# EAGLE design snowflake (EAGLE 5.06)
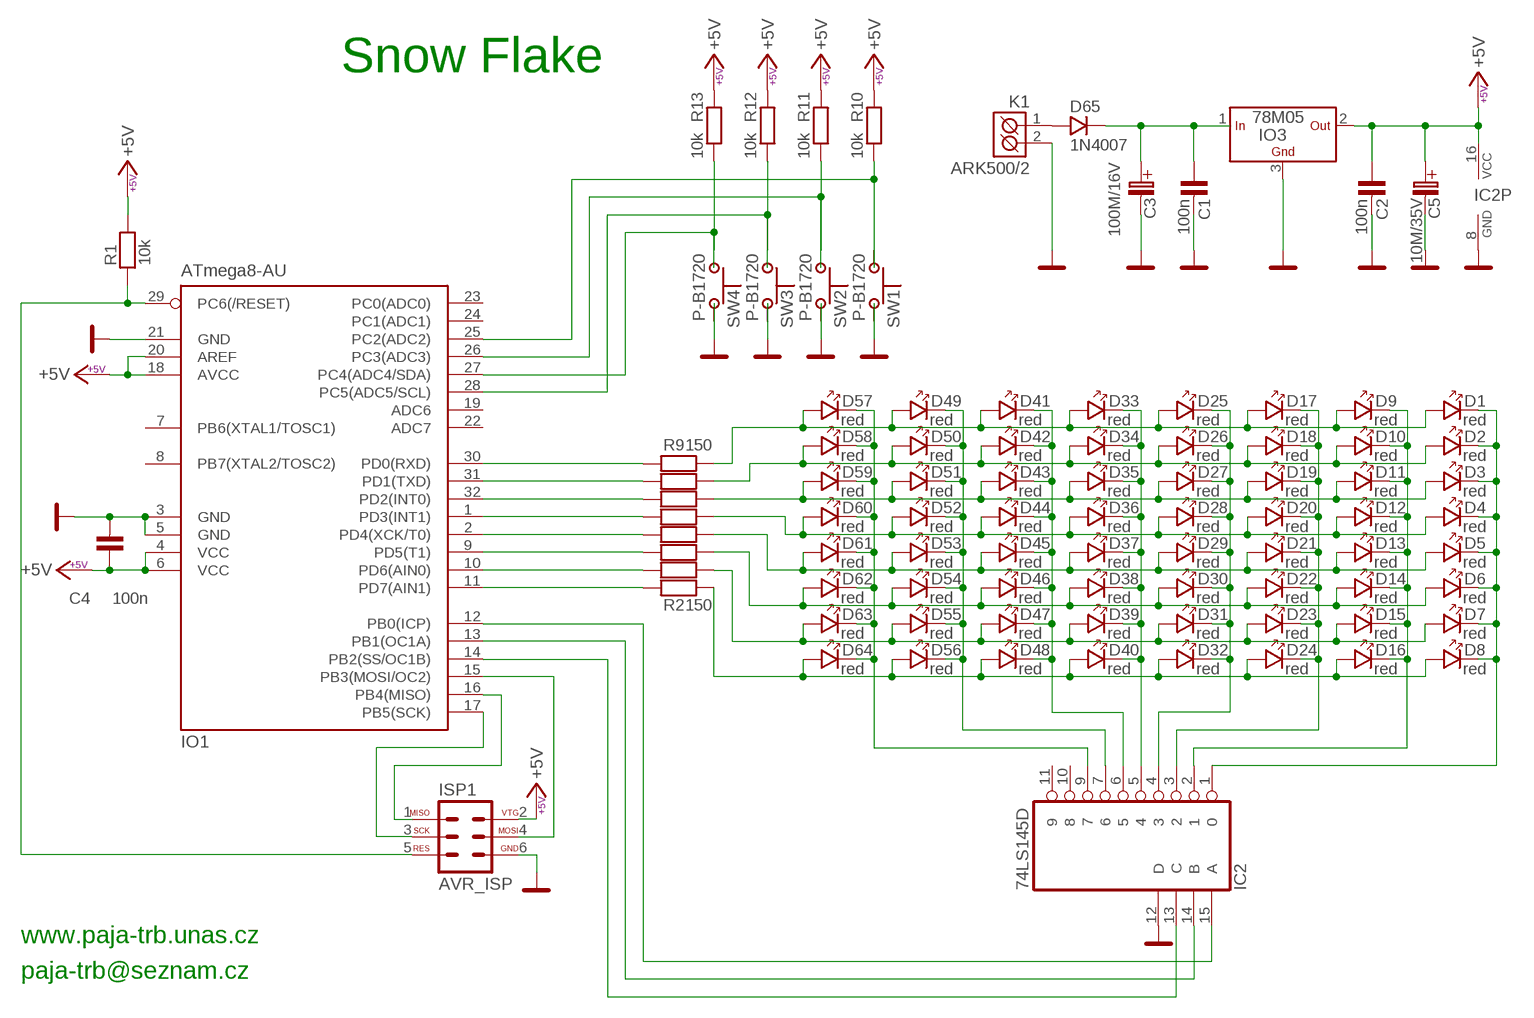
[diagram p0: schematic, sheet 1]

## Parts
C1  100n  C-KERAMIK_SMD_1206  [1206]
C2  100n  C-KERAMIK_SMD_1206  [1206]
C3  100M/16V  100M/16V_SMD  [C_EL-SMD_D]
C4  100n  C-KERAMIK_SMD_1206  [1206]
C5  10M/35V  10M/35V_SMD  [C_EL-SMD_C]
D1  red  LED_5  [LED_5]
D2  red  LED_5  [LED_5]
D3  red  LED_5  [LED_5]
D4  red  LED_5  [LED_5]
D5  red  LED_5  [LED_5]
D6  red  LED_5  [LED_5]
D7  red  LED_5  [LED_5]
D8  red  LED_5  [LED_5]
D9  red  LED_5  [LED_5]
D10  red  LED_5  [LED_5]
D11  red  LED_5  [LED_5]
D12  red  LED_5  [LED_5]
D13  red  LED_5  [LED_5]
D14  red  LED_5  [LED_5]
D15  red  LED_5  [LED_5]
D16  red  LED_5  [LED_5]
D17  red  LED_5  [LED_5]
D18  red  LED_5  [LED_5]
D19  red  LED_5  [LED_5]
D20  red  LED_5  [LED_5]
D21  red  LED_5  [LED_5]
D22  red  LED_5  [LED_5]
D23  red  LED_5  [LED_5]
D24  red  LED_5  [LED_5]
D25  red  LED_5  [LED_5]
D26  red  LED_5  [LED_5]
D27  red  LED_5  [LED_5]
D28  red  LED_5  [LED_5]
D29  red  LED_5  [LED_5]
D30  red  LED_5  [LED_5]
D31  red  LED_5  [LED_5]
D32  red  LED_5  [LED_5]
D33  red  LED_5  [LED_5]
D34  red  LED_5  [LED_5]
D35  red  LED_5  [LED_5]
D36  red  LED_5  [LED_5]
D37  red  LED_5  [LED_5]
D38  red  LED_5  [LED_5]
D39  red  LED_5  [LED_5]
D40  red  LED_5  [LED_5]
D41  red  LED_5  [LED_5]
D42  red  LED_5  [LED_5]
D43  red  LED_5  [LED_5]
D44  red  LED_5  [LED_5]
D45  red  LED_5  [LED_5]
D46  red  LED_5  [LED_5]
D47  red  LED_5  [LED_5]
D48  red  LED_5  [LED_5]
D49  red  LED_5  [LED_5]
D50  red  LED_5  [LED_5]
D51  red  LED_5  [LED_5]
D52  red  LED_5  [LED_5]
D53  red  LED_5  [LED_5]
D54  red  LED_5  [LED_5]
D55  red  LED_5  [LED_5]
D56  red  LED_5  [LED_5]
D57  red  LED_5  [LED_5]
D58  red  LED_5  [LED_5]
D59  red  LED_5  [LED_5]
D60  red  LED_5  [LED_5]
D61  red  LED_5  [LED_5]
D62  red  LED_5  [LED_5]
D63  red  LED_5  [LED_5]
D64  red  LED_5  [LED_5]
D65  1N4007  1N4007_SM-1  [SM-1]
IC2  74LS145D  74145D  [SO16]
IO1  ATmega8-AU  MEGA8-AI  [TQFP32-08]
IO3  78M05  78_SMD_SMD  [D2PAK]
ISP1  AVR_ISP  [MLW06G]
K1  ARK500/2  [ARK500/2]
R1  10k  R_SMD_1206  [1206]
R2  150  R_SMD_1206  [1206]
R3  150  R_SMD_1206  [1206]
R4  150  R_SMD_1206  [1206]
R5  150  R_SMD_1206  [1206]
R6  150  R_SMD_1206  [1206]
R7  150  R_SMD_1206  [1206]
R8  150  R_SMD_1206  [1206]
R9  150  R_SMD_1206  [1206]
R10  10k  R_SMD_1206  [1206]
R11  10k  R_SMD_1206  [1206]
R12  10k  R_SMD_1206  [1206]
R13  10k  R_SMD_1206  [1206]
SW1  P-B1720  [P-B1720]
SW2  P-B1720  [P-B1720]
SW3  P-B1720  [P-B1720]
SW4  P-B1720  [P-B1720]

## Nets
+: D65.A K1.1(K1)
+5V: C2.1 C4.1 C5.+(C_EL+) IC2.16(VCC) IO1.4(VCC) IO1.6(VCC) IO1.18(AVCC) IO1.20(AREF) IO3.2(OUT) ISP1.2 R1.2 R10.1 R11.1 R12.1 R13.1
GND: C1.2 C2.2 C3.-(C_EL-) C4.2 C5.-(C_EL-) IC2.8(GND) IC2.12(D) IO1.3(GND) IO1.5(GND) IO1.21(GND) IO3.3(GND) ISP1.6 K1.2(K2) SW1.2 SW1.4 SW2.2 SW2.4 SW3.2 SW3.4 SW4.2 SW4.4
N$1: IO1.29(PC6(/RESET)) ISP1.5 R1.1
N$2: D5.A D13.A D21.A D29.A D37.A D45.A D53.A D61.A R5.2
N$4: IO1.27(PC4(ADC4/SDA)) R13.2 SW4.1 SW4.3
N$5: IO1.11(PD7(AIN1)) R2.1
N$6: IO1.10(PD6(AIN0)) R3.1
N$7: IO1.9(PD5(T1)) R4.1
N$8: IO1.2(PD4(XCK/T0)) R5.1
N$9: IO1.1(PD3(INT1)) R6.1
N$10: IO1.32(PD2(INT0)) R7.1
N$11: IO1.31(PD1(TXD)) R8.1
N$12: IO1.30(PD0(RXD)) R9.1
N$13: D1.K D2.K D3.K D4.K D5.K D6.K D7.K D8.K IC2.1
N$14: D1.A D9.A D17.A D25.A D33.A D41.A D49.A D57.A R9.2
N$15: D9.K D10.K D11.K D12.K D13.K D14.K D15.K D16.K IC2.2
N$16: D2.A D10.A D18.A D26.A D34.A D42.A D50.A D58.A R8.2
N$17: D3.A D11.A D19.A D27.A D35.A D43.A D51.A D59.A R7.2
N$18: D4.A D12.A D20.A D28.A D36.A D44.A D52.A D60.A R6.2
N$19: D6.A D14.A D22.A D30.A D38.A D46.A D54.A D62.A R4.2
N$20: D7.A D15.A D23.A D31.A D39.A D47.A D55.A D63.A R3.2
N$21: D8.A D16.A D24.A D32.A D40.A D48.A D56.A D64.A R2.2
N$22: D17.K D18.K D19.K D20.K D21.K D22.K D23.K D24.K IC2.3
N$23: D25.K D26.K D27.K D28.K D29.K D30.K D31.K D32.K IC2.4
N$24: D33.K D34.K D35.K D36.K D37.K D38.K D39.K D40.K IC2.5
N$25: D41.K D42.K D43.K D44.K D45.K D46.K D47.K D48.K IC2.6
N$26: D49.K D50.K D51.K D52.K D53.K D54.K D55.K D56.K IC2.7
N$27: D57.K D58.K D59.K D60.K D61.K D62.K D63.K D64.K IC2.9
N$28: IO1.15(PB3(MOSI/OC2)) ISP1.4
N$29: IO1.16(PB4(MISO)) ISP1.1
N$30: IO1.17(PB5(SCK)) ISP1.3
N$31: IO1.28(PC5(ADC5/SCL)) R12.2 SW3.1 SW3.3
N$32: IO1.26(PC3(ADC3)) R11.2 SW2.1 SW2.3
N$33: IO1.25(PC2(ADC2)) R10.2 SW1.1 SW1.3
N$34: IC2.13(C) IO1.14(PB2(SS/OC1B))
N$35: IC2.14(B) IO1.13(PB1(OC1A))
N$36: IC2.15(A) IO1.12(PB0(ICP))
N$38: C1.1 C3.+(C_EL+) D65.K IO3.1(IN)
Unconnected: IC2.10 IC2.11 IO1.7(PB6(XTAL1/TOSC1)) IO1.8(PB7(XTAL2/TOSC2)) IO1.19(ADC6) IO1.22(ADC7) IO1.23(PC0(ADC0)) IO1.24(PC1(ADC1))

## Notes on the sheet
- Snow Flake
- www.paja-trb.unas.cz
- paja-trb@seznam.cz

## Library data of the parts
C1 C2 C4 = #PaJa_31:C-KERAMIK: Kondenzator - keramicky
C3 = #PaJa_C-el_2:100M/16V
C5 = #PaJa_C-el_2:10M/35V
D1-D64 = #PaJa_31:LED: LED - jednobarevna
D65 = #PaJa_31:1N4007: Usmernovaci dioda - 1A, 1000V
IC2 = 74xx-eu:74*145: BCD to decimal DECODER/DRIVER
IO1 = atmel:MEGA8: MICROCONTROLLER 8 Kbytes FLASH, 1 kbytes SRAM, 512 bytes EEPROM, USART, 6-channel 10 bit ADC, 2-channel 8 bit ADC Pin compatible with Atmega48, ATMega88, ATMega168 Source: avr.lbr
IO3 = #PaJa_31:78??: Stabilizátor - 1A a 1,5A ?? - napeti => 05, 06, 08, 09, 12, 15, 18, 20, 24 => 1,5A ?? - napeti => 10, 12, 15, 18 => 1A S ?? - napeti => 05, 09, 10, 12, 15, 18, 24 => 2A T ?? - napeti => 05 => 3A
ISP1 = #PaJa_31:AVR_ISP: AVR ISP konektor (dle standardu)
K1 = #PaJa_konektory:ARK500/2: Svorkovnice - roztec 5mm - dvojita
R1-R13 = #PaJa_31:R: Rezistor
SW1-SW4 = #PaJa_prepinace:P-B1720: &micro;-tlacitko

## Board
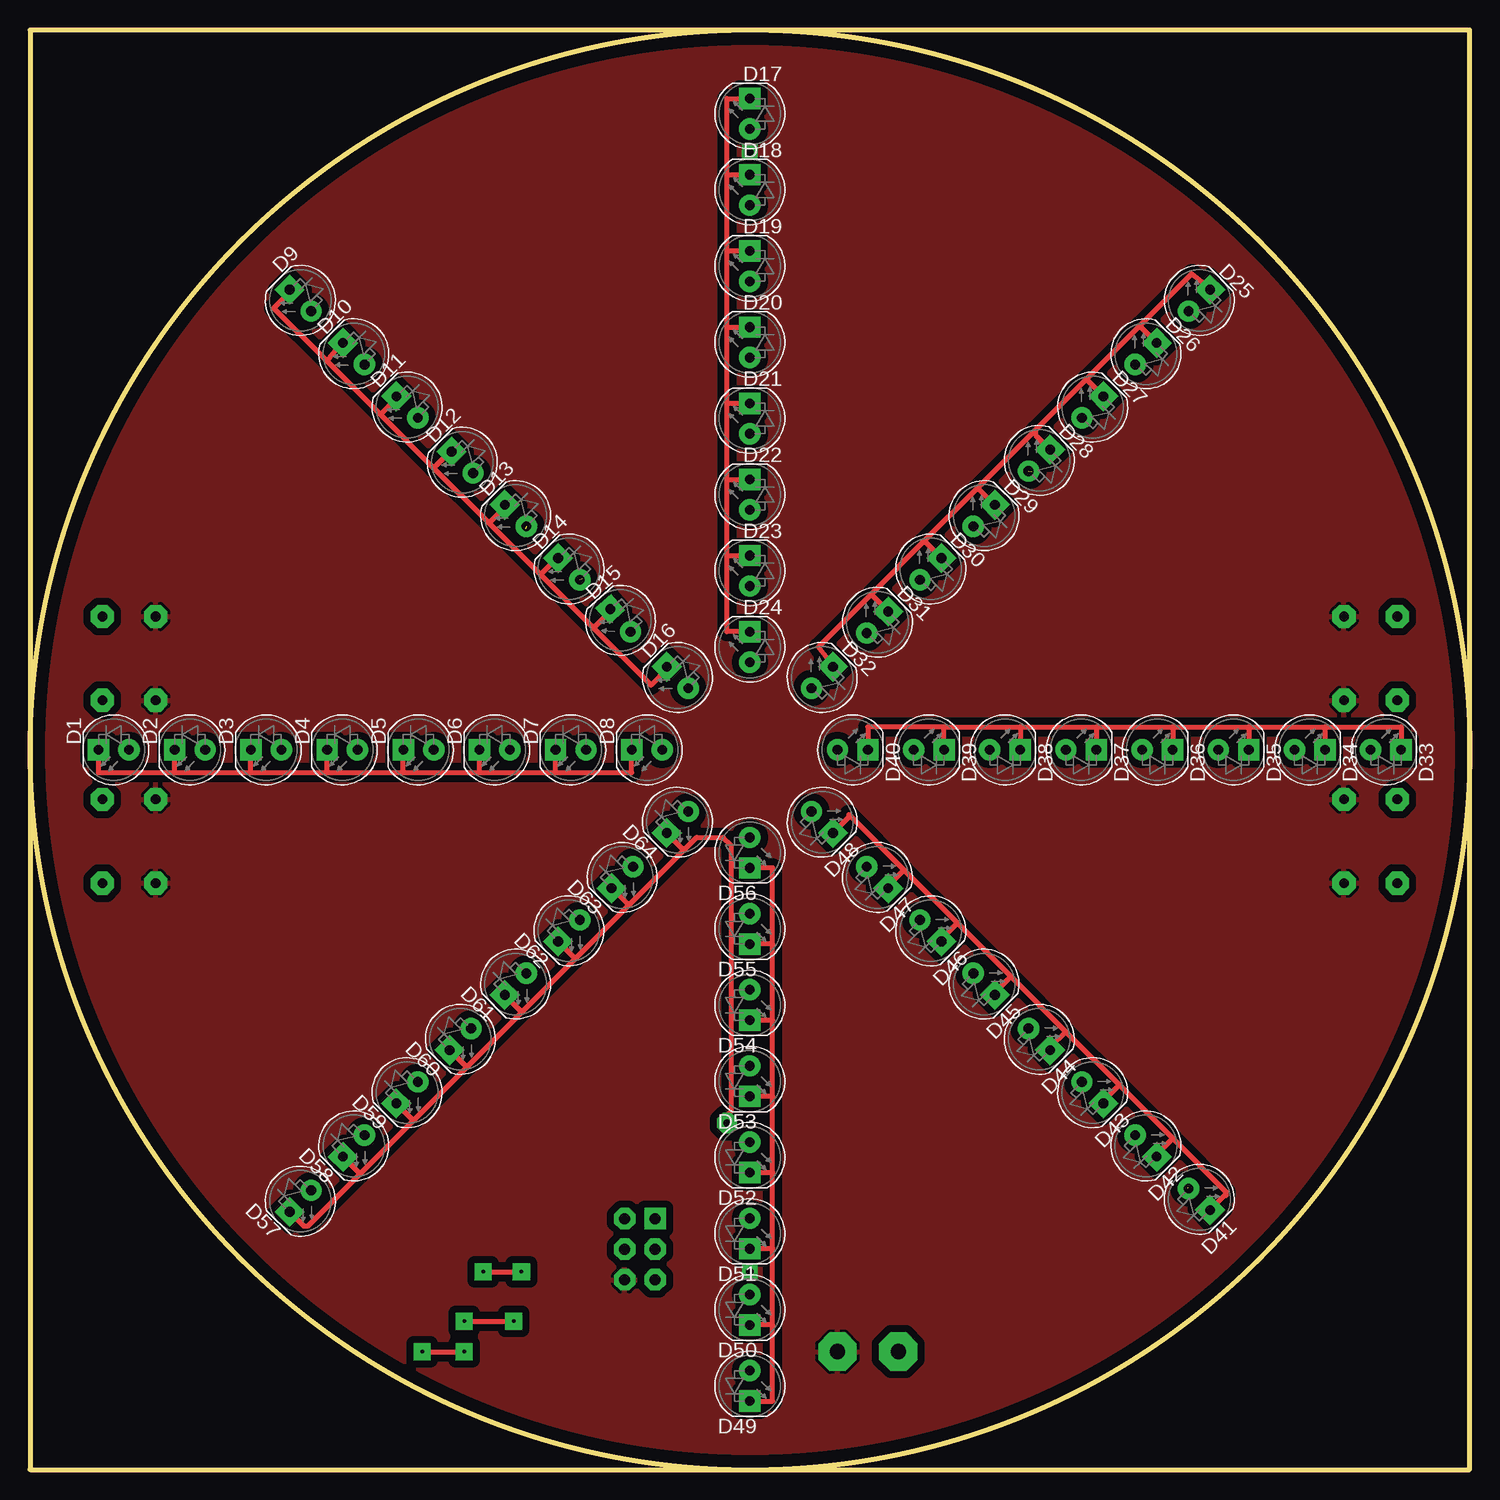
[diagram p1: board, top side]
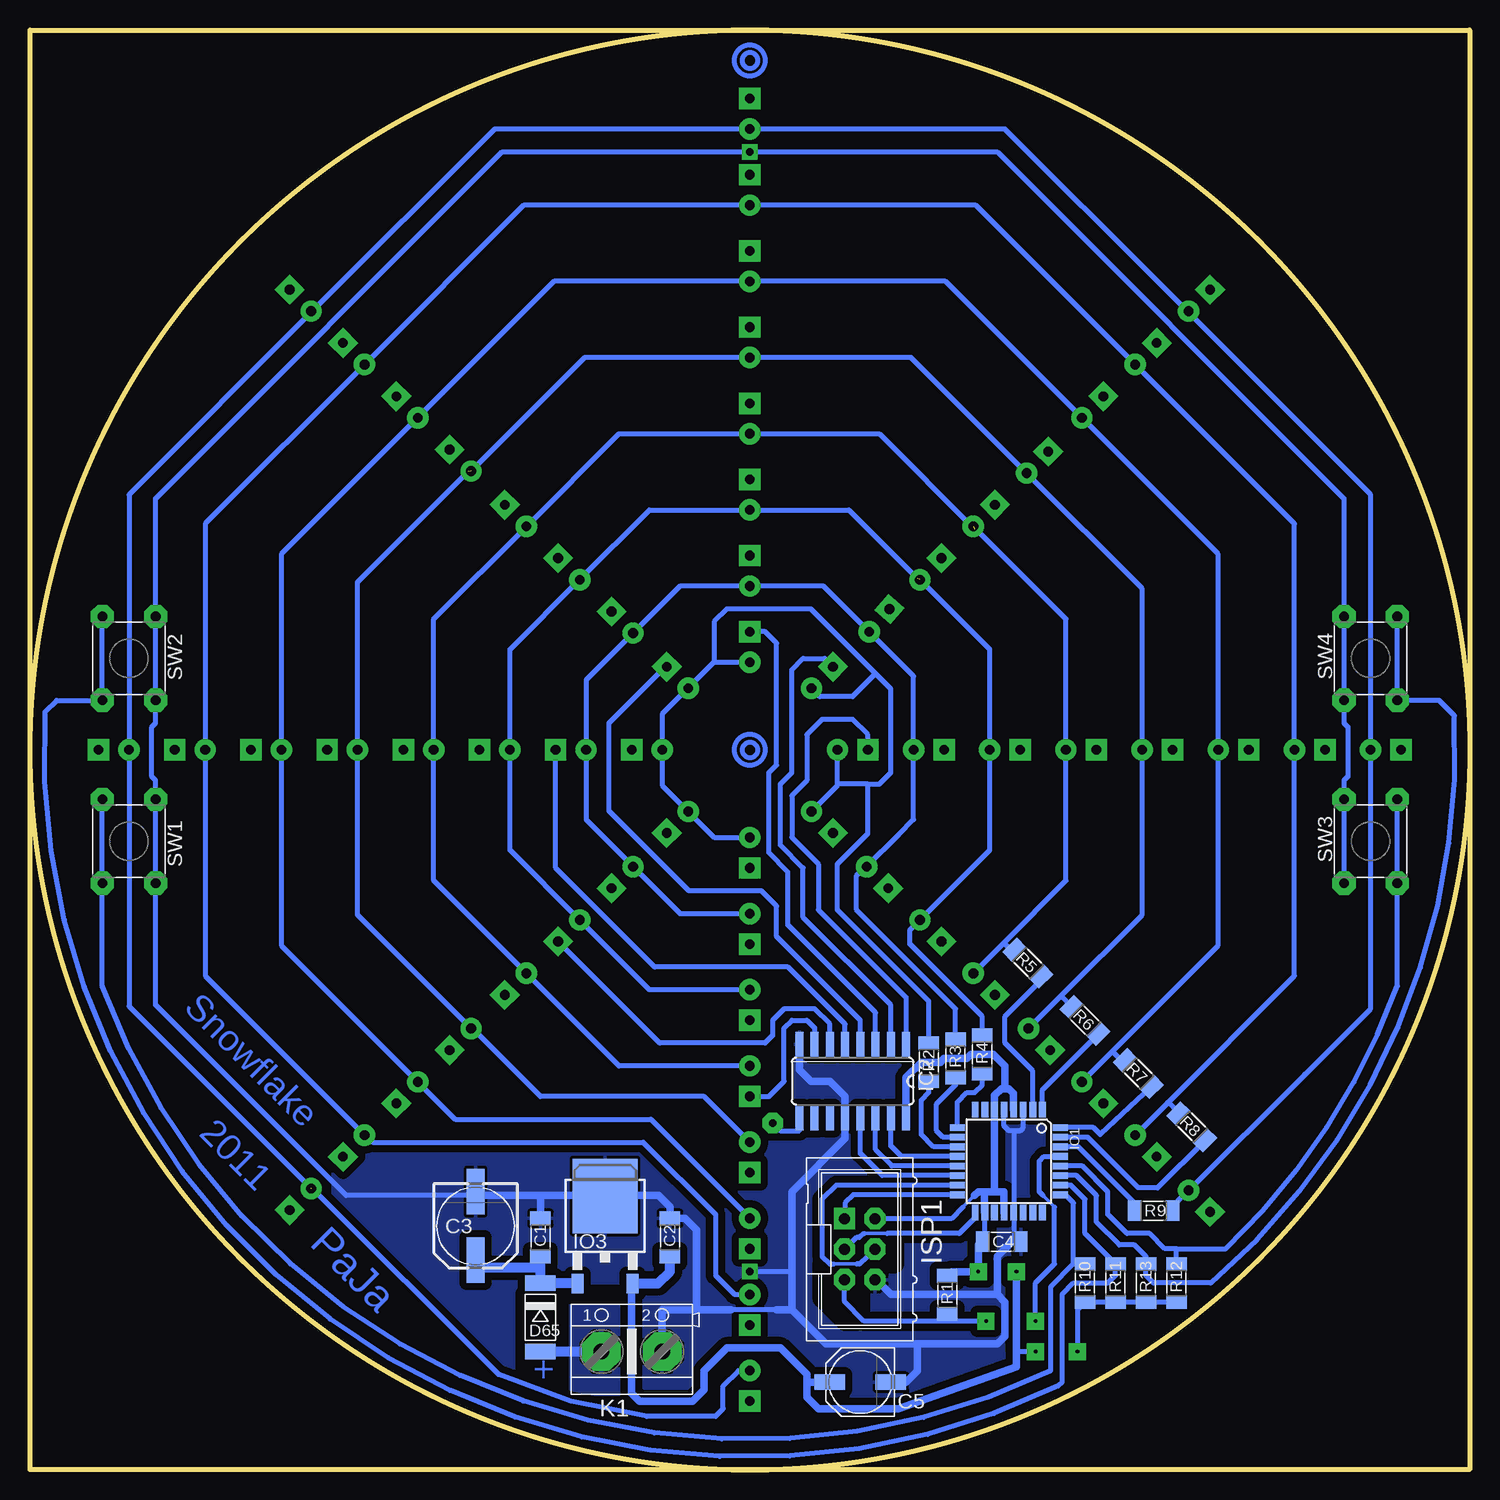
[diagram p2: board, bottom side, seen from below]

Size 120.02 x 120.02 mm. Coordinates in mm from the lower left corner, seen from the top.
Outline: 0,0 120,0 120,120 0,120 0,0
Outline: circle at 60.01,60.01 radius 60.01
Copper layers (1*16): Top 0.035mm / dielectric 1.5mm / Bottom 0.035mm
Design rules "default": minimum track width 10mil, minimum drill 24mil, track to track 8mil, track to pad 8mil, pad to pad 8mil, via to via 8mil, smd to smd 8mil, copper to edge 40mil, drill to drill 8mil, minimum pad ring 10mil, minimum via ring 8mil, stop-mask expansion 4mil, vias tented up to drill 0mil, thermal gap 10mil
bRestrict: 10 lines

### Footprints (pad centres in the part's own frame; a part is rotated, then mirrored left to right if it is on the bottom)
1206 = smd 1.143 x 1.702: 1 -1.587,0; 2 1.587,0
C_EL-SMD_D = smd 3.81 x 1.473: + 2.857,0; - -2.857,0
C_EL-SMD_C = smd 2.54 x 1.27: + 2.54,0; - -2.54,0
LED_5 = drill 0.813 pad 1.778 round: A -1.27,0 | drill 0.813 pad 1.778 square: K 1.27,0
SM-1 = smd 1.27 x 2.54: A 2.857,0; K -2.857,0
SO16 = smd 0.66 x 2.032: 1 -4.445,-3.073; 2 -3.175,-3.073; 3 -1.905,-3.073; 4 -0.635,-3.073; 5 0.635,-3.073; 6 1.905,-3.073; 7 3.175,-3.073; 8 4.445,-3.073; 9 4.445,3.073; 10 3.175,3.073; 11 1.905,3.073; 12 0.635,3.073; 13 -0.635,3.073; 14 -1.905,3.073; 15 -3.175,3.073; 16 -4.445,3.073
TQFP32-08 = smd 1.27 x 0.559: 1 -4.293,2.8; 2 -4.293,2; 3 -4.293,1.2; 4 -4.293,0.4; 5 -4.293,-0.4; 6 -4.293,-1.2; 7 -4.293,-2; 8 -4.293,-2.8; 17 4.293,-2.8; 18 4.293,-2; 19 4.293,-1.2; 20 4.293,-0.4; 21 4.293,0.4; 22 4.293,1.2; 23 4.293,2; 24 4.293,2.8 | smd 0.559 x 1.27: 9 -2.8,-4.293; 10 -2,-4.293; 11 -1.2,-4.293; 12 -0.4,-4.293; 13 0.4,-4.293; 14 1.2,-4.293; 15 2,-4.293; 16 2.8,-4.293; 25 2.8,4.293; 26 2,4.293; 27 1.2,4.293; 28 0.4,4.293; 29 -0.4,4.293; 30 -1.2,4.293; 31 -2,4.293; 32 -2.8,4.293
D2PAK = smd 1 x 1.6: 1 -2.28,-4.8; 2 2.28,-4.8 | smd 5.4 x 6.2: 3 0,2.5
MLW06G = drill 0.914 pad 1.778 square: 1 -2.54,-1.27 | drill 0.914 pad 1.778 octagon: 2 -2.54,1.27; 3 0,-1.27; 4 0,1.27; 5 2.54,-1.27; 6 2.54,1.27
ARK500/2 = drill 1.27 pad 3.2 octagon: 1 -2.54,0; 2 2.54,0
P-B1720 = drill 0.813 pad 1.93 octagon: 1 -3.493,-2.223; 2 -3.493,2.223; 3 3.493,-2.223; 4 3.493,2.223

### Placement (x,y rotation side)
C1  77.47,19.37 90 bottom
C2  66.67,19.37 90 bottom
C3  82.87,20.32 270 bottom
C4  39.02,19 0 bottom
C5  50.8,7.3 180 bottom
D1  6.99,60.01 180 top
D2  13.34,60.01 180 top
D3  19.68,60.01 180 top
D4  26.04,60.01 180 top
D5  32.38,60.01 180 top
D6  38.73,60.01 180 top
D7  45.09,60.01 180 top
D8  51.44,60.01 180 top
D9  22.54,97.47 135 top
D10  26.99,93.03 135 top
D11  31.43,88.58 135 top
D12  36.04,83.98 135 top
D13  40.48,79.53 135 top
D14  44.93,75.09 135 top
D15  49.21,70.8 131.7 top
D16  53.98,66.04 135 top
D17  60.01,113.03 90 top
D18  60.01,106.68 90 top
D19  60.01,100.33 90 top
D20  60.01,93.98 90 top
D21  60.01,87.63 90 top
D22  60.01,81.28 90 top
D23  60.01,74.93 90 top
D24  60.01,68.58 90 top
D25  97.47,97.47 45 top
D26  93.03,93.03 45 top
D27  88.58,88.58 45 top
D28  84.14,84.14 45 top
D29  79.53,79.53 45 top
D30  75.09,75.09 45 top
D31  70.64,70.64 45 top
D32  66.04,66.04 45 top
D33  113.03,60.01 0 top
D34  106.68,60.01 0 top
D35  100.33,60.01 0 top
D36  93.98,60.01 0 top
D37  87.63,60.01 0 top
D38  81.28,60.01 0 top
D39  74.93,60.01 0 top
D40  68.58,60.01 0 top
D41  97.47,22.54 315 top
D42  93.03,26.99 315 top
D43  88.58,31.43 315 top
D44  84.14,35.88 315 top
D45  79.53,40.48 315 top
D46  75.09,44.93 315 top
D47  70.64,49.37 315 top
D48  66.04,53.98 315 top
D49  60.01,6.99 270 top
D50  60.01,13.34 270 top
D51  60.01,19.68 270 top
D52  60.01,26.04 270 top
D53  60.01,32.38 270 top
D54  60.01,38.73 270 top
D55  60.01,45.09 270 top
D56  60.01,51.44 270 top
D57  22.54,22.38 225 top
D58  26.99,26.99 225 top
D59  31.43,31.43 225 top
D60  35.88,35.88 225 top
D61  40.48,40.48 225 top
D62  44.93,44.93 225 top
D63  49.37,49.37 225 top
D64  53.98,53.98 225 top
D65  77.47,12.7 270 bottom
IC2  51.44,32.38 180 bottom
IO1  38.42,25.72 270 bottom
IO3  72.07,20.32 0 bottom
ISP1  50.85,18.38 270 bottom
K1  69.85,9.84 0 bottom
R1  43.55,14.57 90 bottom
R2  45.09,33.97 89.9 bottom
R3  42.86,34.29 90 bottom
R4  40.64,34.61 90 bottom
R5  36.83,42.23 135 bottom
R6  32.07,37.47 135 bottom
R7  27.62,33.02 135 bottom
R8  23.18,28.57 135 bottom
R9  26.35,21.59 0 bottom
R10  32.07,15.56 90 bottom
R11  29.53,15.56 90 bottom
R12  24.45,15.56 90 bottom
R13  26.99,15.56 90 bottom
SW1  111.76,52.39 270 bottom
SW2  111.76,67.63 270 bottom
SW3  8.26,52.39 90 bottom
SW4  8.26,67.63 90 bottom

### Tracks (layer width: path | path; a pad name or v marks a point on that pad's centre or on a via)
+
  Bottom 0.813: K1.1 D65.A
  pour Bottom (isolate 0.61): 70.8,6.35 70.8,13.97 74.93,13.97 74.93,6.35
+5V  (via drill 0.3 pad 1.42)
  Top 0.406: v37.78,16.51 v40.96,16.51 | v32.7,9.84 v36.2,9.84
  Bottom 0.305: 41.27,22.86 42.23,21.91
  Bottom 0.406: 40.44,21.47 IO1.18 40.42,19.19 C4.1 | ISP1.2 43.22,20.92 42.23,21.91 | 39.69,23.18 39.62,23.18 | R12.1 R13.1 R11.1 R10.1 32.7,13.34 v32.7,9.84 | v36.2,9.84 37.78,9.84
  Bottom 0.61: 40.44,21.47 40.44,23.18 | IO1.20 38.82,23.18 39.69,23.18 40.44,23.18 | 39.62,23.18 IO1.6 39.62,31.18 39.05,31.75 38.73,31.75 | 40.44,23.18 40.96,23.18 41.27,22.86 | IC2.16 46.99,32.7 45.72,33.97 44.13,33.97 43.81,34.29 41.91,34.29 41.59,34.61 39.69,34.61 38.73,33.66 38.73,31.75 | v37.78,16.51 37.78,9.84 37.78,8.57 47.62,5.08 54.29,5.08 55.24,6.03 55.24,7.3 | IO3.2 69.85,15.46 69.85,6.35 69.22,5.71 64.77,5.71 63.82,6.67 63.82,8.26 61.91,10.16 57.47,10.16 55.24,7.94 55.24,7.3 | 55.24,7.3 C5.+ | C4.1 40.69,19 40.96,18.73 v40.96,16.51 43.18,16.51 43.55,16.14 R1.2 | 38.73,31.75 38.42,31.75 38.02,31.35 IO1.4
  Bottom 0.813: C2.1 66.67,16.51 67.67,15.52 IO3.2
GND  (via drill 0.6 pad 1.27)
  Bottom 0.406: 37.97,27.07 | 37.97,21.44 IO1.21 | 37.97,21.44 37.97,27.07 | 37.97,21.44 37.97,18.91 C4.2 | SW4.2 10.48,62.23 10.16,61.91 10.16,57.78 10.48,57.47 SW3.4 SW3.2 | SW1.2 109.54,57.47 109.86,57.78 109.86,61.91 109.54,62.23 109.54,62.55 SW2.4 SW2.2 109.54,80.96 80.64,109.86 v60.01,109.86 39.37,109.86 10.48,80.96 SW4.4 | SW1.4 109.54,38.73 93.66,22.86 83.19,22.86 C3.- | SW1.4 SW1.2 | SW4.4 SW4.2 | C4.2 37.8,19.05 | 38.15,19 C4.2 | 57.78,13.34 61.59,13.34 | 56.52,16.51 v60.01,16.51 | SW4.4 SW4.2 | IO1.3 37.22,28.5 37.47,28.26 | IO1.5 38.82,28.66 38.42,28.26 37.47,28.26 | 37.97,27.07 37.97,28.26 37.47,28.26 | SW1.4 SW1.2
  Bottom 0.61: IC2.8 55.88,33.34 54.93,32.38 53.34,32.38 52.07,31.11 IC2.12 52.07,27.62 56.52,23.18 56.52,16.51 56.52,13.34 | 38.15,19 39.37,17.78 39.37,14.61 | 77.47,22.86 C1.2 | 77.47,22.86 72.11,22.86 IO3.3 72.03,22.86 67.63,22.86 66.67,21.91 C2.2 65.41,20.95 64.45,20 64.45,13.34 | 77.47,22.86 82.55,22.86 C3.- | K1.2 67.31,13.34 64.45,13.34 | 61.59,13.34 64.45,13.34 | 56.52,13.34 57.78,13.34 | 56.52,13.34 53.66,10.48 46.04,10.48 | C5.- 46.99,7.3 46.04,8.26 46.04,10.48 | 46.04,10.48 39.37,10.48 38.73,11.11 38.73,13.97 39.37,14.61 | 39.37,14.61 48.26,14.61 49.49,15.84 ISP1.6
  pour Bottom (isolate 0.61): 94.93,0 94.61,37.47 31.43,37.47 31.75,0
  pour Top (isolate 0.61): 0,120.02 120.02,120.02 120.02,0 0,0
N$1  (via drill 0.3 pad 1.42)
  Top 0.406: v36.2,12.38 v40.32,12.38
  Bottom 0.305: 34.61,21.91 35.56,22.86
  Bottom 0.406: IO1.29 35.48,26.12 35.88,25.72 35.88,23.18 35.56,22.86 | 34.61,21.91 34.61,17.14 36.2,15.56 v36.2,12.38 | v40.32,12.38 43.5,12.38 | 43.5,12.38 43.46,12.66 R1.1 | ISP1.5 52.12,14.02 50.48,12.38 43.5,12.38
N$2  (1 unrouted)
  Bottom 0.406: 38.84,43.92 D61.A | 38.84,43.92 33.66,49.1 D5.A 33.66,70.91 D13.A | 41.27,78.42 49.21,86.36 D21.A 70.91,86.36 D29.A 86.36,70.91 D37.A 86.36,49.1 D45.A 70.91,33.66 D53.A | R5.2 38.27,43.35 38.84,43.92
N$4
  Bottom 0.406: IO1.27 32.77,24.52 31.11,22.86 31.11,20.64 29.21,18.73 27.94,18.73 26.99,17.78 R13.2 26.99,16.19 26.35,15.56 21.59,15.56 arc-52 1.27,62.87 2.54,64.14 SW4.1 SW4.3
N$5
  Bottom 0.406: IO1.11 44.7,26.92 45.72,27.94 45.72,30.8 45.09,31.43 R2.1
N$6
  Bottom 0.406: R3.1 42.86,32.07 44.45,30.48 44.45,28.26 43.91,27.72 IO1.10
N$7
  Bottom 0.406: 40.64,32.7 R4.1 40.64,32.07 41.27,31.43 41.91,31.43 42.71,30.63 IO1.9
N$8
  Bottom 0.406: R5.1 35.71,40.81 38.73,37.78 38.73,35.56 36.42,33.24 IO1.2
N$9
  Bottom 0.406: 30.97,36.34 R6.1 35.62,31.67 IO1.1
N$10
  Bottom 0.406: R7.1 26.52,31.9 30.8,27.94 31.38,28.52 IO1.32
N$11
  Bottom 0.406: R8.1 26.04,23.5 | IO1.31 31.84,27.72 27.62,23.5 26.04,23.5 | 26.04,23.5 26.03,23.49
N$12
  Bottom 0.406: IO1.30 32.63,26.92 27.94,22.23 R9.1
N$13
  Top 0.406: 31.11,58.1 37.47,58.1 | 37.47,58.1 43.81,58.1 | 43.81,58.1 50.16,58.1 D8.K | 43.81,58.1 D7.K | 37.47,58.1 D6.K | 31.11,58.1 D5.K | 12.06,58.1 18.41,58.1 | 18.41,58.1 24.77,58.1 | 24.77,58.1 31.11,58.1 | 12.06,58.1 D2.K | 18.41,58.1 D3.K | 24.77,58.1 D4.K | 12.06,58.1 5.71,58.1 D1.K
  Bottom 0.406: IC2.1 46.99,39.37 54.29,46.67 54.29,50.48 56.52,52.7 56.52,56.2 55.24,57.47 55.24,61.28 53.98,62.55 51.44,62.55 50.16,61.28 D8.K
N$14  (1 unrouted)
  Bottom 0.406: R9.2 24.33,22.39 D57.A 23.39,23.28 13.97,32.7 | D41.A 111.76,38.63 D33.A 111.76,81.28 96.52,96.52 | 25.72,98.74 8.26,81.28 D1.A 8.26,38.42 13.97,32.7 | 25.72,98.74 38.73,111.76 D17.A 81.28,111.76 96.52,96.52 | D9.A 23.55,96.57 25.72,98.74 | 13.97,32.7 13.65,33.02 | 96.52,23.5 80.96,7.94 74.93,5.71 68.58,4.45 62.87,4.45 62.23,5.08 62.23,6.99 60.96,8.26 D49.A | 96.52,96.52 D25.A
N$15
  Top 0.406: D10.K 25.98,93.92 24.77,92.39 | 29.21,87.95 24.77,92.39 | 33.66,83.5 29.21,87.95 | 38.26,78.9 33.66,83.5 | 42.55,74.61 38.26,78.9 | 46.99,70.17 42.55,74.61 | 46.99,70.17 51.75,65.41 53.08,66.73 D16.K | D11.K 30.53,89.27 29.21,87.95 | D12.K 35.03,84.88 33.66,83.5 | D13.K 39.58,80.22 38.26,78.9 | D14.K 43.92,75.99 42.55,74.61 | D15.K 48.37,71.55 46.99,70.17 | 24.77,92.39 20.32,96.84 21.64,98.16 D9.K
  Bottom 0.406: IC2.2 48.26,38.73 55.56,46.04 55.56,50.16 57.47,52.07 57.47,57.15 56.52,58.1 56.52,66.67 55.56,67.63 53.77,67.63 D16.K
N$16
  Bottom 0.406: D58.A 25.35,30.43 | 25.35,30.43 25.12,30.65 R8.2 | 25.35,30.43 14.61,41.17 D2.A 14.61,78.85 D10.A 41.17,105.41 D18.A 78.85,105.41 D26.A 105.41,78.85 D34.A 105.41,41.17 D42.A 92.02,27.89 91.44,27.3 68.9,27.3 62.87,21.27 62.87,16.19 61.28,14.61 D50.A
N$17
  Bottom 0.406: D59.A 29.79,34.87 | 29.79,34.87 20.95,43.71 D3.A 20.95,76.31 D11.A 43.71,99.06 D19.A 76.31,99.06 D27.A 99.06,76.31 D35.A 99.06,43.71 D43.A 84.56,29.21 68.26,29.21 D51.A | R7.2 29.06,34.14 29.79,34.87
N$18  (1 unrouted)
  Bottom 0.406: 34.08,39.47 27.3,46.25 D4.A 27.3,73.45 D12.A 46.56,92.71 D20.A 73.77,92.71 D28.A | D60.A 34.08,39.47 | 83.5,83.19 92.71,73.98 D36.A 92.71,46.25 D44.A 83.13,36.78 77.47,31.11 63.82,31.11 D52.A | 34.08,39.47 R6.2
N$19  (1 unrouted)
  Bottom 0.406: 43.13,48.52 D62.A 46.67,44.98 46.67,43.81 40.64,37.78 R4.2 | 43.13,48.52 40.01,51.64 D6.A 40.01,68.37 D14.A | 46.04,74.3 51.75,80.01 D22.A 68.37,80.01 D30.A 80.01,68.37 D38.A 80.01,51.64 D46.A 68.37,40.01 D54.A | 43.13,48.52
N$20
  Bottom 0.406: 47.57,52.97 D63.A 50.38,50.27 51.12,49.53 51.12,46.67 42.86,38.42 R3.2 | 47.57,52.97 46.35,54.18 D7.A 46.35,66.15 D15.A 53.86,73.66 D23.A 65.83,73.66 D31.A 73.66,65.83 D39.A 73.66,54.18 D47.A 65.83,46.35 D55.A | 47.57,52.97
N$21
  Bottom 0.406: 62.97,67.31 D32.A 67.31,62.97 D40.A 67.31,57.04 D48.A 62.97,52.7 D56.A | D64.A 52.7,57.04 52.7,57.15 | 52.7,57.15 D8.A | 62.97,67.31 62.97,70.69 61.91,71.75 54.93,71.75 49.53,66.36 | 62.97,67.31 D24.A | 49.53,66.36 48.26,65.09 48.26,58.1 49.21,57.15 | 50.16,57.15 52.7,57.15 | D16.A 54.18,64.45 51.44,64.45 49.53,66.36 | R2.2 45.08,39.05 52.7,46.67 52.7,50.48 50.16,53.02 50.16,57.15 | 49.21,57.15 | 50.16,57.15 49.21,57.15
N$22
  Top 0.406: 58.1,76.2 58.1,69.85 D24.K | 58.1,76.2 58.1,82.55 | 58.1,82.55 58.1,88.9 | 58.1,88.9 58.1,95.25 | 58.1,95.25 D20.K | 58.1,88.9 D21.K | 58.1,82.55 D22.K | 58.1,76.2 D23.K | 58.1,95.25 58.1,101.6 | 58.1,101.6 58.1,107.95 | 58.1,107.95 58.1,114.3 D17.K | 58.1,107.95 D18.K | 58.1,101.6 D19.K
  Bottom 0.406: IC2.3 49.53,38.1 56.83,45.4 56.83,49.85 58.42,51.44 58.42,58.1 57.78,58.74 57.78,68.9 58.74,69.85 D24.K
N$23
  Top 0.406: D25.K 98.37,98.48 96.84,99.69 92.55,95.41 | 70.17,73.03 65.72,68.58 66.94,67.05 D32.K | 70.17,73.03 74.45,77.31 | 74.45,77.31 78.9,81.76 | 78.9,81.76 83.82,86.68 | 83.82,86.68 88.11,90.96 | 88.11,90.96 92.55,95.41 | D31.K 70.17,72.92 70.17,73.03 | D30.K 74.66,77.31 74.45,77.31 | D29.K 79.11,81.76 78.9,81.76 | D26.K 92.55,95.3 92.55,95.41 | D27.K 88.11,90.86 88.11,90.96 | D28.K 83.82,86.25 83.82,86.68
  Bottom 0.406: IC2.4 50.8,37.47 57.78,44.45 57.78,46.99 59.05,48.26 65.09,48.26 71.75,54.93 71.75,62.23 67.05,66.94 D32.K
N$24
  Top 0.406: D33.K 114.3,61.91 107.95,61.91 | 76.2,61.91 69.85,61.91 D40.K | 76.2,61.91 82.55,61.91 | 82.55,61.91 88.9,61.91 | 88.9,61.91 95.25,61.91 | 95.25,61.91 101.6,61.91 | 101.6,61.91 107.95,61.91 | D39.K 76.2,61.91 | 82.55,61.91 D38.K | 88.9,61.91 D37.K | 107.95,61.91 D34.K | 101.6,61.91 D35.K | 95.25,61.91 D36.K
  Bottom 0.406: IC2.5 52.07,37.15 56.83,41.91 67.94,41.91 76.2,50.16 D39.K
N$25
  Top 0.406: D41.K 99.59,22.86 99.69,22.86 99.69,23.18 95.25,27.62 | 72.87,50.01 68.26,54.61 68.26,54.4 D48.K | 77.31,45.56 72.87,50.01 | 77.31,45.56 81.76,41.12 | 81.76,41.12 86.36,36.51 | 86.36,36.51 90.81,32.07 | 90.81,32.07 95.25,27.62 | D47.K 71.54,48.68 72.87,50.01 | D46.K 75.99,44.24 77.31,45.56 | D45.K 80.43,39.79 81.76,41.12 | D44.K 85.03,35.19 86.36,36.51 | D43.K 89.48,30.74 90.81,32.07 | D42.K 93.92,26.3 95.25,27.62
  Bottom 0.406: IC2.6 53.34,37.15 54.61,38.42 57.15,38.42 58.1,37.47 58.1,36.2 58.74,35.56 67.52,35.56 D46.K
N$26
  Top 0.406: 61.91,37.47 D54.K | 61.91,37.47 61.91,43.81 | 61.91,43.81 61.91,50.16 D56.K | D49.K 61.91,5.71 61.91,12.06 | 61.91,12.06 61.91,18.41 | 61.91,18.41 61.91,24.77 | 61.91,24.77 61.91,31.11 | 61.91,31.11 61.91,37.47 | 61.91,31.11 D53.K | 61.91,24.77 D52.K | 61.91,18.41 D51.K | 61.91,12.06 D50.K | 61.91,43.81 D55.K
  Bottom 0.406: IC2.7 54.61,36.83 55.24,37.47 56.52,37.47 57.15,36.83 57.15,32.38 58.42,31.11 D53.K
N$27  (via drill 0.6 pad 1.68)
  Top 0.406: 27.46,24.61 23.18,20.32 22.81,20.32 D57.K | 27.46,24.61 32.07,29.21 | 32.07,29.21 36.51,33.66 | 36.51,33.66 41.12,38.26 | 41.12,38.26 45.4,42.55 | 45.4,42.55 50.01,47.15 | D58.K 27.46,24.71 27.46,24.61 | D59.K 31.86,29.21 32.07,29.21 | D60.K 36.3,33.66 36.51,33.66 | D61.K 40.91,38.26 41.12,38.26 | D62.K 45.4,42.65 45.4,42.55 | D63.K 49.8,47.15 50.01,47.15 | 50.01,47.15 54.61,51.75 | 54.61,51.75 55.56,52.7 57.78,52.7 58.42,52.07 58.42,29.84 58.1,29.53 v58.1,28.89 | D64.K 54.4,51.75 54.61,51.75
  Bottom 0.406: v58.1,28.89 57.47,28.26 55.88,28.26 IC2.9
N$28
  Bottom 0.305: 53.02,17.14 50.88,17.14
  Bottom 0.406: IO1.15 52.8,23.72 53.98,22.54 53.98,17.78 53.34,17.14 53.02,17.14 | ISP1.4 50.88,17.14 51.12,17.14
N$29
  Bottom 0.406: IO1.16 51.38,22.92 52.07,22.23 52.07,20.97 ISP1.1
N$30
  Bottom 0.305: 48.58,19.68 50.48,19.68
  Bottom 0.406: 41.22,21.33 IO1.17 41.27,21.37 41.27,20.95 42.55,19.68 48.58,19.68 | ISP1.3 51.12,19.37 50.88,19.37 50.48,19.68
N$31
  Bottom 0.406: IO1.28 32.3,25.32 30.16,23.18 30.16,21.27 28.57,19.68 26.67,19.68 25.4,18.41 24.45,18.41 | R12.2 24.45,18.41 | SW3.3 SW3.1 6.03,40.32 arc26 20.32,18.41 24.45,18.41
N$32
  Bottom 0.406: IO1.26 33.24,23.72 32.07,22.54 32.07,19.68 R11.2 29.53,16.19 30.16,15.56 33.02,15.56 33.97,14.61 33.97,7.3 34.29,6.99 arc119 118.75,63.18 117.79,64.14 SW2.3 SW2.1
N$33
  Bottom 0.406: IO1.25 33.71,22.92 33.02,22.23 33.02,17.14 | 33.02,17.14 R10.2 | 33.02,17.14 34.92,15.24 34.92,8.26 arc96 113.98,40.32 SW1.3 | SW1.3 SW1.1 SW1.3
N$34
  Bottom 0.406: IC2.13 50.8,26.35 48.97,24.52 IO1.14
N$35
  Bottom 0.406: IC2.14 49.53,26.67 48.18,25.32 IO1.13
N$36
  Bottom 0.406: IC2.15 48.26,26.99 47.39,26.12 IO1.12
N$38
  Bottom 0.61: 77.43,15.52 D65.K
  Bottom 0.813: D65.K 77.47,16.83 | IO3.1 77.43,15.52 | 77.47,16.83 C1.1 | 77.47,16.83 82.87,16.83 C3.+
(copper drawn outside any net)
  shapes: Bottom circle x4

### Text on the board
Bottom: Snowflake | 2011 | PaJa | +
